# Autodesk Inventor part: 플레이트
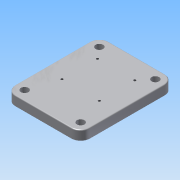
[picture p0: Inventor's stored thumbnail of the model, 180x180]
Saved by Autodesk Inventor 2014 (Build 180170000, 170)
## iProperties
Created: 2017-10
Part Number: 플레이트
Material: 알루미늄 6061
Document SubType Name: Modeling
Designer: mduedu
Density: 2.71 g/cm^3
Mass: 208.312 g
Surface Area: 199.832 cm^2
Volume: 76.8677 cm^3
Appearance: 알루미늄 - 평지
Author: mduedu
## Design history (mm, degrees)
sketch "스케치1"
  geometry: L1 (50, 40)-(-50, 40); L2 (-50, 40)-(-50, -40); L3 (-50, -40)-(50, -40); L4 (50, -40)-(50, 40); L5 (50, 40)-(-50, -40); L6 (-50, 40)-(50, -40); 1 further point
  constraints: 12 end point, 2 midpoint, 2 parallel, 1 horizontal, 1 perpendicular
  dimensions: "d0" = 100 distance of L3.end L2.end; "d1" = 80 distance of L2.end L1.end
extrude "돌출1" new body sketch "스케치1" distance "d2" = 10; taper "d3" = 0 deg
fillet "모깎기1" dims "d4" = 10
sketch "스케치2"
  geometry: L1 (40, 40)-(-40, 40) reference; L2 (-50, 30)-(-50, -30) reference; L3 (-40, -40)-(40, -40) reference; L4 (50, -30)-(50, 30) reference; L5 (-50, 0)-(50, 0); A1 r 10 centre (40, 30) between (50, 30) and (40, 40) reference; A2 r 10 centre (-40, 30) between (-40, 40) and (-50, 30) reference; A3 r 10 centre (-40, -30) between (-50, -30) and (-40, -40) reference; A4 r 10 centre (40, -30) between (40, -40) and (50, -30) reference; 4 further points
  constraints: 2 end point, 2 midpoint, 2 symmetric about line, 1 horizontal alignment
  dimensions: "d12" = 22 distance from line of point (28, 20) L4; "d13" = 38 distance of point (-10, 20) point (28, 20); "d14" = 20 distance from line of point (28, 20) L5
hole "구멍1" sketch "스케치2" at (-10, 20), (28, 20), (28, -20), (-10, -20) diameter "d5" = 2.459; stored, may be unused: countersink angle "d9" = 90 deg, drill point angle "d11" = 120 deg; dims "d6" = 12.312, "d7" = 4, "d8" = 2, "d10" = 13.812
fillet "모깎기2" dims "d15" = 1
sketch "스케치3"
  geometry: C1 r 4 at (-40, 30); C2 r 4 at (40, 30); C3 r 4 at (40, -30); C4 r 4 at (-40, -30); A1 r 10 centre (-40, 30) between (-40, 40) and (-50, 30) reference; A2 r 10 centre (40, 30) between (50, 30) and (40, 40) reference; A3 r 10 centre (40, -30) between (40, -40) and (50, -30) reference; A4 r 10 centre (-40, -30) between (-50, -30) and (-40, -40) reference; 1 further point
  constraints: 4 centre point, 4 coincident, 3 equal radius
  dimensions: "d16" = 8 diameter of C1
extrude "돌출2" cut sketch "스케치3" stored distance "d17" = 10; taper "d18" = 0 deg
node "솔리드1"
node "투영된 루프1"
